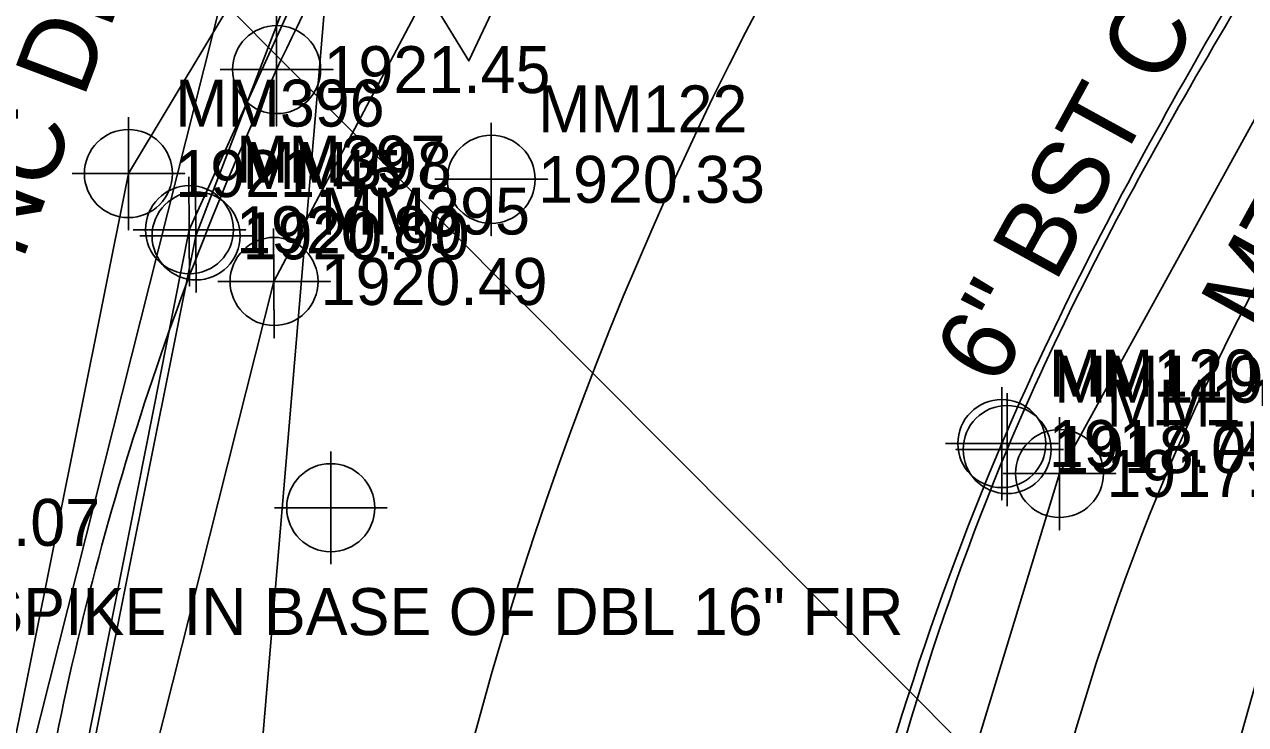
# Model space of a CAD drawing. Extents: x 1004514 to 1005247, y 553695 to 554706.
# Drawn here: x 1005003.6 to 1005068.7, y 554190.9 to 554228.2 of the extents above; entities that cross this region are included whole.
import ezdxf

# ---------------------------------------------------------------- set-up
doc = ezdxf.new("R2010")
doc.units = 0
for name, color, linetype in [('COGO Default Chain', 7, 'Continuous'), ('COGO Default Curve', 7, 'Continuous'), ('Cogo Default Point CELL', 7, 'Continuous'), ('CTL Primary Horizontal and Vertical Leader', 7, 'Continuous'), ('CTL Vertical Benchmark Cogo Comment', 7, 'Continuous'), ('CTL Vertical Benchmark Cogo Elevation', 7, 'Continuous'), ('Exist DTM Crownline Cogo Elevation', 7, 'Continuous'), ('Exist DTM Crownline Cogo Number', 7, 'Continuous'), ('Exist DTM Crownline Cogo Point CELL', 7, 'Continuous'), ('Exist Guardrail', 7, 'Continuous'), ('Exist Guardrail Cogo Elevation', 7, 'Continuous'), ('Exist Guardrail Cogo Number', 7, 'Continuous'), ('Exist Guardrail Cogo Point CELL', 7, 'Continuous'), ('Exist Guardrail Text', 7, 'Continuous'), ('Exist Horizontal Alignment', 7, 'Continuous'), ('Exist Right of Way Line', 7, 'Continuous'), ('Exist Roads Curbs', 7, 'Continuous'), ('Exist Roads Curbs Cogo Elevation', 7, 'Continuous'), ('Exist Roads Curbs Cogo Number', 7, 'Continuous'), ('Exist Roads Curbs Cogo Point CELL', 7, 'Continuous'), ('Exist Roads Curbs Text', 7, 'Continuous'), ('Exist Roads EOP', 7, 'Continuous'), ('Exist Roads EOP Cogo Elevation', 7, 'Continuous'), ('Exist Roads EOP Cogo Number', 7, 'Continuous'), ('Exist Roads EOP Cogo Point CELL', 7, 'Continuous'), ('Exist Structure Minor Drop Inlet Text', 7, 'Continuous'), ('Exist Structure Minor Pipes CMP 30 Inch', 7, 'Continuous'), ('Exist Structure Minor Pipes CMP 30 Inch Invert', 7, 'Continuous'), ('Exist Utilities Telephone UG Conduit SUE LOS B', 7, 'Continuous'), ('Exist Utilities Telephone UG Conduit SUE LOS B Cogo Elevation', 7, 'Continuous'), ('Exist Utilities Telephone UG Conduit SUE LOS B Cogo Number', 7, 'Continuous'), ('Exist Utilities Telephone UG Conduit SUE LOS B Cogo Point CELL', 7, 'Continuous'), ('Exist Utilities Telephone UG FO SUE LOS C', 7, 'Continuous'), ('Exist Utilities Telephone UG FO SUE LOS C Cogo Elevation', 7, 'Continuous'), ('Exist Utilities Telephone UG FO SUE LOS C Cogo Number', 7, 'Continuous'), ('Exist Utilities Telephone UG FO SUE LOS C Cogo Point CELL', 7, 'Continuous'), ('Exist Vegetation Woods Line', 7, 'Continuous'), ('Old_Level_3', 7, 'Continuous'), ('Scratch_Level_3', 7, 'Continuous')]:
    doc.layers.add(name, color=color, linetype=linetype)

msp = doc.modelspace()

# ---------------------------------------------------------------- linework, layer by layer
at = {"layer": 'COGO Default Chain'}
msp.add_line((1004974.9, 553701.543), (1005020.282, 554237.182), dxfattribs=at)
msp.add_arc((1005209.198, 554141.741), 188, 143.26447, 181.15854, dxfattribs=at)
at = {"layer": 'COGO Default Curve'}
msp.add_arc((1005209.198, 554141.741), 188, 143.26447, 181.15854, dxfattribs=at)
at = {"layer": 'Cogo Default Point CELL'}
for points in [[(1005019.931, 554205.466), (1005019.931, 554202.466)], [(1005016.931, 554202.466), (1005019.931, 554202.466)], [(1005019.931, 554202.466), (1005022.931, 554202.466)], [(1005019.931, 554202.466), (1005019.931, 554199.466)]]:
    msp.add_lwpolyline(points, dxfattribs=at)
msp.add_circle((1005019.931, 554202.466), 2.344, dxfattribs=at)
at = {"layer": 'CTL Primary Horizontal and Vertical Leader'}
msp.add_lwpolyline([(1005022.291, 554234.394), (1005027.295, 554226.252), (1005028.822, 554229.491)], dxfattribs=at)
at = {"layer": 'Exist DTM Crownline Cogo Point CELL'}
msp.add_lwpolyline([(1005028.479, 554222.945), (1005028.479, 554216.945), (1005028.479, 554219.945), (1005031.479, 554219.945), (1005025.479, 554219.945)], dxfattribs=at)
msp.add_circle((1005028.479, 554219.945), 2.344, dxfattribs=at)
at = {"layer": 'Exist Guardrail'}
msp.add_lwpolyline([(1005077.879, 554238.993), (1005058.749, 554204.287), (1005049.992, 554175.596), (1005045.293, 554142.756), (1005044.111, 554102.438), (1005045.04, 554055.452), (1005045.63, 554011.474), (1005045.274, 553965.154), (1005039.583, 553916.738), (1005028.889, 553873.019)], dxfattribs=at)
at = {"layer": 'Exist Guardrail Cogo Point CELL'}
msp.add_lwpolyline([(1005058.749, 554207.287), (1005058.749, 554201.287), (1005058.749, 554204.287), (1005061.749, 554204.287), (1005055.749, 554204.287)], dxfattribs=at)
msp.add_circle((1005058.749, 554204.287), 2.344, dxfattribs=at)
at = {"layer": 'Exist Horizontal Alignment'}
msp.add_arc((1005209.198, 554141.741), 188, 143.26447, 181.15854, dxfattribs=at)
at = {"layer": 'Exist Right of Way Line'}
msp.add_arc((1005209.198, 554141.741), 238, 143.26447, 181.15854, dxfattribs=at)
at = {"layer": 'Exist Roads Curbs'}
msp.add_spline([(1005075.03, 554240.325), (1005055.961, 554205.561), (1005046.997, 554176.639), (1005041.862, 554143.203), (1005041.439, 554133.575)], degree=3, dxfattribs=at)
at = {"layer": 'Exist Roads Curbs Cogo Point CELL'}
msp.add_lwpolyline([(1005055.961, 554208.561), (1005055.961, 554202.561), (1005055.961, 554205.561), (1005053.23, 554205.561), (1005058.961, 554205.561)], dxfattribs=at)
msp.add_circle((1005055.961, 554205.561), 2.344, dxfattribs=at)
at = {"layer": 'Exist Roads EOP'}
for points in [[(1005026.381, 554243.671), (1005017.049, 554225.785), (1005004.478, 554185.698), (1005001.445, 554147.868), (1005001.025, 554103.612), (1005002.785, 554054.517)], [(1005074.494, 554240.581), (1005055.678, 554205.88), (1005046.35, 554176.623), (1005041.386, 554143.248), (1005040.93, 554132.857)]]:
    msp.add_spline(points, degree=3, dxfattribs=at)
at = {"layer": 'Exist Roads EOP Cogo Point CELL'}
for points in [[(1005017.049, 554228.785), (1005017.049, 554222.785), (1005017.049, 554225.785), (1005020.049, 554225.785), (1005014.049, 554225.785)], [(1005055.678, 554208.88), (1005055.678, 554202.88), (1005055.678, 554205.88), (1005058.678, 554205.88), (1005052.678, 554205.88)]]:
    msp.add_lwpolyline(points, dxfattribs=at)
for centre in [(1005017.049, 554225.785), (1005055.678, 554205.88)]:
    msp.add_circle(centre, 2.344, dxfattribs=at)
at = {"layer": 'Exist Structure Minor Pipes CMP 30 Inch'}
msp.add_line((1005009.937, 554233.672), (1005074.79, 554168.593), dxfattribs=at)
at = {"layer": 'Exist Utilities Telephone UG Conduit SUE LOS B'}
for points in [[(1004986.625, 553881.898), (1004994.172, 553936.442), (1004994.355, 553983.339), (1004992.834, 554032.196), (1004992.187, 554082.209), (1005000.242, 554139.11), (1005002.91, 554167.939), (1005012.741, 554216.936), (1005031.231, 554265.036), (1005060.708, 554304.647)], [(1004986.909, 553881.957), (1004994.669, 553936.387), (1004995.066, 553983.404), (1004993.502, 554032.182), (1004992.704, 554081.89), (1004999.846, 554139.17), (1005002.6, 554167.938), (1005012.391, 554217.264), (1005034.093, 554264.981), (1005060.823, 554304.66)], [(1004996.466, 553880.309), (1005003.636, 553934.419), (1005005.075, 553983.38), (1005003.635, 554031.726), (1005001.159, 554081.826), (1005001.307, 554137.229), (1005005.127, 554167.881), (1005016.898, 554214.508), (1005037.162, 554252.759), (1005044.72, 554267.983), (1005066.683, 554300.275)]]:
    msp.add_lwpolyline(points, dxfattribs=at)
at = {"layer": 'Exist Utilities Telephone UG Conduit SUE LOS B Cogo Point CELL'}
for points in [[(1005012.375, 554220.078), (1005012.408, 554214.264), (1005012.391, 554217.264), (1005015.408, 554217.264), (1005009.408, 554217.264)], [(1005012.725, 554219.751), (1005012.758, 554213.936), (1005012.741, 554216.936), (1005015.758, 554216.936), (1005009.758, 554216.936)], [(1005016.882, 554217.322), (1005016.915, 554211.508), (1005016.898, 554214.508), (1005019.915, 554214.508), (1005013.915, 554214.508)]]:
    msp.add_lwpolyline(points, dxfattribs=at)
for centre in [(1005012.408, 554217.264), (1005012.758, 554216.936), (1005016.915, 554214.508)]:
    msp.add_circle(centre, 2.344, dxfattribs=at)
at = {"layer": 'Exist Utilities Telephone UG FO SUE LOS C'}
msp.add_lwpolyline([(1004993.352, 553880.974), (1004999.906, 553935.306), (1005000.501, 553983.286), (1004999.325, 554031.271), (1004996.571, 554081.46), (1004996.427, 554140.051), (1004998.713, 554168.32), (1005009.154, 554220.252), (1005037.109, 554266.749), (1005065.185, 554302.194)], dxfattribs=at)
at = {"layer": 'Exist Utilities Telephone UG FO SUE LOS C Cogo Point CELL'}
msp.add_lwpolyline([(1005009.154, 554223.252), (1005009.154, 554217.252), (1005009.154, 554220.252), (1005012.154, 554220.252), (1005006.154, 554220.252)], dxfattribs=at)
msp.add_circle((1005009.154, 554220.252), 2.344, dxfattribs=at)
at = {"layer": 'Exist Vegetation Woods Line'}
msp.add_lwpolyline([(1005043.245, 553870.571), (1005060.795, 553939.084), (1005067.553, 553999.387), (1005060.697, 554075.478), (1005056.834, 554134.404), (1005061.711, 554166.622), (1005070.29, 554196.972), (1005092.518, 554231.451), (1005101.443, 554246.608), (1005128.922, 554275.434)], dxfattribs=at)
at = {"layer": 'Old_Level_3'}
msp.add_arc((1005179.657, 554155.763), 125, 145.93577, 181.58005, dxfattribs=at)
at = {"layer": 'Scratch_Level_3'}
msp.add_line((1004952.617, 553985.711), (1005030.054, 554292.752), dxfattribs=at)

# ---------------------------------------------------------------- texts
at = {"layer": 'CTL Vertical Benchmark Cogo Comment'}
msp.add_text('RR SPIKE IN BASE OF DBL 16" FIR', height=2.5, dxfattribs=at).set_placement((1004995.564, 554195.686))
at = {"layer": 'CTL Vertical Benchmark Cogo Elevation'}
msp.add_text('1927.07', height=2.5, dxfattribs=at).set_placement((1004995.564, 554200.436))
at = {"layer": 'Exist DTM Crownline Cogo Elevation'}
msp.add_text('1920.33', height=2.5, dxfattribs=at).set_placement((1005030.979, 554218.695))
at = {"layer": 'Exist DTM Crownline Cogo Number'}
msp.add_text('MM122', height=2.5, dxfattribs=at).set_placement((1005030.979, 554222.445))
at = {"layer": 'Exist Guardrail Cogo Elevation'}
msp.add_text('1917.26', height=2.5, dxfattribs=at).set_placement((1005061.249, 554203.037))
at = {"layer": 'Exist Guardrail Cogo Number'}
msp.add_text('MM118', height=2.5, dxfattribs=at).set_placement((1005061.249, 554206.787))
at = {"layer": 'Exist Guardrail Text'}
msp.add_text('MTL', height=4, rotation=61.1368, dxfattribs=at).set_placement((1005069.61, 554211.561))
at = {"layer": 'Exist Roads Curbs Cogo Elevation'}
msp.add_text('1918.05', height=2.5, dxfattribs=at).set_placement((1005058.461, 554204.311))
at = {"layer": 'Exist Roads Curbs Cogo Number'}
msp.add_text('MM119', height=2.5, dxfattribs=at).set_placement((1005058.461, 554208.061))
at = {"layer": 'Exist Roads Curbs Text'}
msp.add_text('6" BST CURB', height=4, rotation=61.25355, dxfattribs=at).set_placement((1005055.455, 554208.797))
at = {"layer": 'Exist Roads EOP Cogo Elevation'}
for s, p in [('1921.45', (1005019.549, 554224.535)), ('1917.74', (1005058.178, 554204.63))]:
    msp.add_text(s, height=2.5, dxfattribs=at).set_placement(p)
at = {"layer": 'Exist Roads EOP Cogo Number'}
msp.add_text('MM120', height=2.5, dxfattribs=at).set_placement((1005058.178, 554208.38))
at = {"layer": 'Exist Structure Minor Drop Inlet Text'}
msp.add_text('CONC DI', height=4, rotation=69.35798, dxfattribs=at).set_placement((1005000.682, 554208.075))
at = {"layer": 'Exist Structure Minor Pipes CMP 30 Inch Invert'}
msp.add_text("INV=1914.63'", height=4, rotation=68.30682, dxfattribs=at).set_placement((1004995.039, 554211.294))
at = {"layer": 'Exist Utilities Telephone UG Conduit SUE LOS B Cogo Elevation'}
for s, p in [('1920.89', (1005014.891, 554216.014)), ('1920.90', (1005015.241, 554215.686)), ('1920.49', (1005019.398, 554213.258))]:
    msp.add_text(s, height=2.5, dxfattribs=at).set_placement(p)
at = {"layer": 'Exist Utilities Telephone UG Conduit SUE LOS B Cogo Number'}
for s, p in [('MM397', (1005014.891, 554219.764)), ('MM398', (1005015.241, 554219.436)), ('MM395', (1005019.398, 554217.008))]:
    msp.add_text(s, height=2.5, dxfattribs=at).set_placement(p)
at = {"layer": 'Exist Utilities Telephone UG FO SUE LOS C Cogo Elevation'}
msp.add_text('1921.45', height=2.5, dxfattribs=at).set_placement((1005011.654, 554219.002))
at = {"layer": 'Exist Utilities Telephone UG FO SUE LOS C Cogo Number'}
msp.add_text('MM396', height=2.5, dxfattribs=at).set_placement((1005011.654, 554222.752))

doc.saveas('drawing.dxf')
